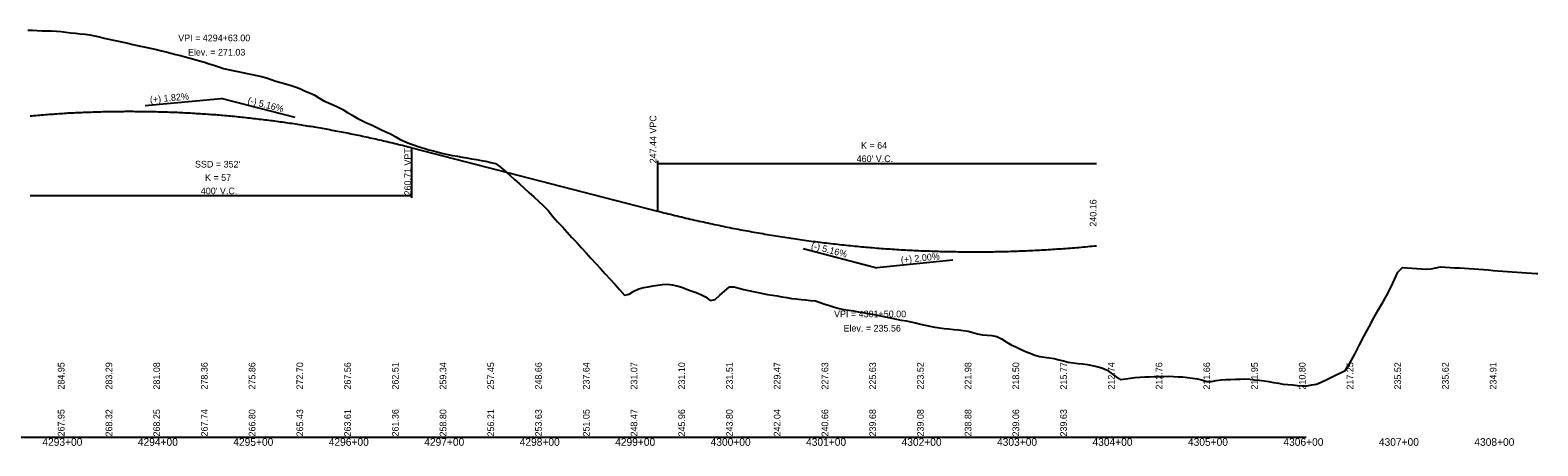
# Model space of a CAD drawing. Extents: x 1838386 to 1955906, y 719739 to 834437.
# Drawn here: x 1916207 to 1917787, y 768480 to 768916 of the extents above; entities that cross this region are included whole.
import ezdxf

# ---------------------------------------------------------------- set-up
doc = ezdxf.new("R2010")
doc.units = 0
for name, color, linetype in [('RD_DDB_GradeTX', 7, 'Continuous'), ('RD_DDB_Profile_EX', 7, 'Continuous'), ('RD_DDB_Profile_Lbl', 7, 'Continuous'), ('RD_DDB_Profile_PR', 7, 'Continuous'), ('RD_DDB_StaTX', 7, 'Continuous'), ('RD_DDB_StripGrade', 7, 'Continuous'), ('RD_DDB_VCLbl', 7, 'Continuous'), ('RD_GPK_Profile_Cell', 7, 'Continuous')]:
    doc.layers.add(name, color=color, linetype=linetype)

msp = doc.modelspace()

# ---------------------------------------------------------------- linework, layer by layer
at = {"layer": 'RD_DDB_GradeTX'}
for p, q in [((1916327.6, 768837.1), (1916407.2, 768844.3)), ((1916484.7, 768824.3), (1916407.2, 768844.3)), ((1917016.8, 768686.9), (1917094.2, 768666.9)), ((1917173.8, 768674.9), (1917094.2, 768666.9))]:
    msp.add_line(p, q, dxfattribs=at)
at = {"layer": 'RD_DDB_Profile_EX'}
for points in [[(1916204.7, 768916), (1916209.7, 768915.8), (1916214.7, 768915.6), (1916219.7, 768915.4), (1916224.7, 768915.3), (1916229.7, 768915.1), (1916234.7, 768914.9), (1916239.7, 768914.4), (1916244.7, 768913.8), (1916249.7, 768913.3), (1916254.7, 768912.7), (1916259.7, 768912.2), (1916264.7, 768911.7), (1916269.7, 768911), (1916274.7, 768909.9), (1916279.7, 768908.8), (1916284.7, 768907.7), (1916289.7, 768906.6), (1916294.7, 768905.5), (1916299.7, 768904.4), (1916304.7, 768903.3), (1916309.7, 768902.2), (1916314.7, 768901.1), (1916319.7, 768900), (1916324.7, 768898.9), (1916329.7, 768897.8), (1916334.7, 768896.7), (1916339.7, 768895.6), (1916344.7, 768894.4), (1916349.7, 768893.3), (1916354.7, 768892), (1916359.7, 768890.6), (1916364.7, 768889.3), (1916369.7, 768887.9), (1916374.7, 768886.5), (1916379.7, 768885.1), (1916384.7, 768883.8)], [(1916384.7, 768883.8), (1916389.7, 768882.4), (1916394.7, 768880.8), (1916399.7, 768879.2), (1916404.7, 768877.5), (1916409.7, 768875.9), (1916414.7, 768874.8), (1916419.7, 768873.7), (1916424.7, 768872.7), (1916429.7, 768871.6), (1916434.7, 768870.6), (1916439.7, 768869.5), (1916444.7, 768868.3), (1916449.7, 768867.2), (1916454.7, 768866), (1916459.7, 768864.2), (1916464.7, 768862.6), (1916469.7, 768861.1), (1916474.7, 768859.7), (1916479.7, 768858.2), (1916484.7, 768856.6), (1916489.7, 768854.8), (1916494.7, 768852.4), (1916499.7, 768850.4), (1916504.7, 768848.1), (1916509.7, 768845), (1916514.7, 768842), (1916519.7, 768839.9), (1916524.7, 768837.6), (1916529.7, 768835.1), (1916534.7, 768832.8), (1916539.7, 768829.7), (1916544.7, 768826.7), (1916549.7, 768823.7), (1916554.7, 768821.2), (1916559.7, 768818.9), (1916564.7, 768816.6), (1916569.7, 768814.2), (1916574.7, 768811.8), (1916579.7, 768809.4), (1916584.7, 768807.1), (1916589.7, 768804.5), (1916594.7, 768801.4), (1916599.7, 768799.1), (1916604.7, 768797.1), (1916609.7, 768795.3), (1916614.7, 768793.7), (1916619.7, 768792.1), (1916624.7, 768790.5), (1916629.7, 768789.3), (1916634.7, 768788), (1916639.7, 768786.8), (1916644.7, 768785.7), (1916649.7, 768784.7), (1916654.7, 768783.7), (1916659.7, 768782.8), (1916664.7, 768782), (1916669.7, 768781.2), (1916674.7, 768780.3), (1916679.7, 768779.4), (1916684.7, 768778.5), (1916689.7, 768777.3), (1916694.7, 768776.3), (1916699.7, 768772.5), (1916704.7, 768768.2), (1916709.7, 768763.8), (1916714.7, 768759.4), (1916719.7, 768754.8), (1916724.7, 768750.1), (1916729.7, 768745.6), (1916734.7, 768741.2), (1916739.7, 768736.7), (1916744.7, 768732), (1916749.7, 768726.7), (1916754.7, 768720.5), (1916759.7, 768715), (1916764.7, 768709.6), (1916769.7, 768704.1), (1916774.7, 768698.7), (1916779.7, 768693.2), (1916784.7, 768687.7), (1916789.7, 768682.3), (1916794.7, 768676.8), (1916799.7, 768671.4), (1916804.7, 768665.9), (1916809.7, 768660.4), (1916814.7, 768655), (1916819.7, 768649.5), (1916824.7, 768643.9), (1916829.7, 768638.1), (1916834.7, 768639.1), (1916839.7, 768642.4), (1916844.7, 768644.7), (1916849.7, 768646), (1916854.7, 768646.9), (1916859.7, 768647.8), (1916864.7, 768648.5), (1916869.7, 768649.3), (1916874.7, 768649.6), (1916879.7, 768648.8), (1916884.7, 768647.9)], [(1917384.7, 768552.8), (1917389.7, 768552.8), (1917394.7, 768552.9), (1917399.7, 768553.1), (1917404.7, 768552.9), (1917409.7, 768552.6), (1917414.7, 768552.4), (1917419.7, 768551.8), (1917424.7, 768551.1), (1917429.7, 768550.4), (1917434.7, 768549.2), (1917439.7, 768547.5), (1917444.7, 768547.4), (1917449.7, 768548.6), (1917454.7, 768549.2), (1917459.7, 768549.5), (1917464.7, 768549.8), (1917469.7, 768550), (1917474.7, 768550.1), (1917479.7, 768550.4), (1917484.7, 768550.1), (1917489.7, 768549.4), (1917494.7, 768548.8), (1917499.7, 768548.2), (1917504.7, 768547.4), (1917509.7, 768546.5), (1917514.7, 768545.7), (1917519.7, 768544.8), (1917524.7, 768544.4), (1917529.7, 768543.9), (1917534.7, 768543.4), (1917539.7, 768543.1), (1917544.7, 768543.1), (1917549.7, 768544), (1917554.7, 768544.8), (1917559.7, 768547), (1917564.7, 768549.4), (1917569.7, 768551.8), (1917574.7, 768554.2), (1917579.7, 768556.6), (1917584.7, 768559), (1917589.7, 768566.6), (1917594.7, 768576.3), (1917599.7, 768585.9), (1917604.7, 768595.5), (1917609.7, 768605), (1917614.7, 768614.4), (1917619.7, 768623.1), (1917624.7, 768631.9), (1917629.7, 768640.6), (1917634.7, 768650.5), (1917639.7, 768662.1), (1917644.7, 768667.2), (1917649.7, 768666.8), (1917654.7, 768666.4), (1917659.7, 768666), (1917664.7, 768665.6), (1917669.7, 768665.3), (1917674.7, 768665.7), (1917679.7, 768666.6), (1917684.7, 768667.8), (1917689.7, 768667.5), (1917694.7, 768667.2), (1917699.7, 768666.9), (1917704.7, 768666.6), (1917709.7, 768666.3), (1917714.7, 768665.9), (1917719.7, 768665.6), (1917724.7, 768665.2), (1917729.7, 768664.9), (1917734.7, 768664.5), (1917739.7, 768664.1), (1917744.7, 768663.7), (1917749.7, 768663.3), (1917754.7, 768662.9), (1917759.7, 768662.5), (1917764.7, 768662.2), (1917769.7, 768661.9), (1917774.7, 768661.5), (1917779.7, 768661.2), (1917784.7, 768660.9), (1917786.5, 768660.7)], [(1916884.7, 768647.9), (1916889.7, 768646.5), (1916894.7, 768644.5), (1916899.7, 768642.6), (1916904.7, 768640.7), (1916909.7, 768638.8), (1916914.7, 768636.4), (1916919.7, 768632.5), (1916924.7, 768633.5), (1916929.7, 768637.9), (1916934.7, 768642.3), (1916939.7, 768646.7), (1916944.7, 768646.7), (1916949.7, 768645.4), (1916954.7, 768643.9), (1916959.7, 768642.9), (1916964.7, 768641.9), (1916969.7, 768640.9), (1916974.7, 768639.8), (1916979.7, 768638.8), (1916984.7, 768638), (1916989.7, 768637.2), (1916994.7, 768636.4), (1916999.7, 768635.6), (1917004.7, 768634.7), (1917009.7, 768634.2), (1917014.7, 768633.7), (1917019.7, 768633.2), (1917024.7, 768632.6), (1917029.7, 768632.1), (1917034.7, 768630.5), (1917039.7, 768628.8), (1917044.7, 768627.1), (1917049.7, 768625.4), (1917054.7, 768624), (1917059.7, 768623.2), (1917064.7, 768622.4), (1917069.7, 768621.5), (1917074.7, 768620.7), (1917079.7, 768619.8), (1917084.7, 768619), (1917089.7, 768618.2), (1917094.7, 768617.2), (1917099.7, 768616.1), (1917104.7, 768615), (1917109.7, 768614), (1917114.7, 768613), (1917119.7, 768612), (1917124.7, 768611), (1917129.7, 768610), (1917134.7, 768608.9), (1917139.7, 768607.8), (1917144.7, 768606.7), (1917149.7, 768605.5), (1917154.7, 768604.4), (1917159.7, 768603.7), (1917164.7, 768603.2), (1917169.7, 768602.7), (1917174.7, 768602.1), (1917179.7, 768601.6), (1917184.7, 768601.1), (1917189.7, 768600.4), (1917194.7, 768598.9), (1917199.7, 768597.4), (1917204.7, 768596.5), (1917209.7, 768596.1), (1917214.7, 768595.7), (1917219.7, 768594.7), (1917224.7, 768592.4), (1917229.7, 768589.3), (1917234.7, 768586.1), (1917239.7, 768583.8), (1917244.7, 768581.4), (1917249.7, 768579), (1917254.7, 768577.1), (1917259.7, 768575.2), (1917264.7, 768573.6), (1917269.7, 768572.9), (1917274.7, 768572.2), (1917279.7, 768571.5), (1917284.7, 768570.4), (1917289.7, 768569.1), (1917294.7, 768567.9), (1917299.7, 768567), (1917304.7, 768566.5), (1917309.7, 768566), (1917314.7, 768565.5), (1917319.7, 768564.4), (1917324.7, 768563.1), (1917329.7, 768561.7), (1917334.7, 768559.9), (1917339.7, 768556.2), (1917344.7, 768552.5), (1917349.7, 768549.5), (1917354.7, 768550.3), (1917359.7, 768551.1), (1917364.7, 768551.8), (1917369.7, 768552.1), (1917374.7, 768552.3), (1917379.7, 768552.6), (1917384.7, 768552.8)]]:
    msp.add_lwpolyline(points, dxfattribs=at)
at = {"layer": 'RD_DDB_Profile_PR'}
msp.add_line((1916607.2, 768792.7), (1916864.2, 768726.3), dxfattribs=at)
for points in [[(1916207.2, 768826.1), (1916215.2, 768826.8), (1916223.2, 768827.5), (1916231.2, 768828), (1916239.2, 768828.6), (1916247.2, 768829.1), (1916255.2, 768829.5), (1916263.2, 768829.8), (1916271.2, 768830.1), (1916279.2, 768830.4), (1916287.2, 768830.6), (1916295.2, 768830.7), (1916303.2, 768830.8), (1916311.2, 768830.9), (1916319.2, 768830.8), (1916327.2, 768830.7), (1916335.2, 768830.6), (1916343.2, 768830.4), (1916351.2, 768830.2), (1916359.2, 768829.9), (1916367.2, 768829.5), (1916375.2, 768829.1), (1916383.2, 768828.6), (1916391.2, 768828.1), (1916399.2, 768827.5), (1916407.2, 768826.9), (1916415.2, 768826.2), (1916423.2, 768825.4), (1916431.2, 768824.6), (1916439.2, 768823.7), (1916447.2, 768822.8), (1916455.2, 768821.8), (1916463.2, 768820.8), (1916471.2, 768819.7), (1916479.2, 768818.6), (1916487.2, 768817.4), (1916495.2, 768816.1), (1916503.2, 768814.8), (1916511.2, 768813.4), (1916519.2, 768812), (1916527.2, 768810.5), (1916535.2, 768809), (1916543.2, 768807.4), (1916551.2, 768805.8), (1916559.2, 768804.1), (1916567.2, 768802.3), (1916575.2, 768800.5), (1916583.2, 768798.6), (1916591.2, 768796.7), (1916599.2, 768794.7), (1916607.2, 768792.7)], [(1916864.2, 768726.3), (1916873.4, 768724), (1916882.6, 768721.7), (1916891.8, 768719.5), (1916901, 768717.3), (1916910.2, 768715.3), (1916919.4, 768713.3), (1916928.6, 768711.3), (1916937.8, 768709.4), (1916947, 768707.6), (1916956.2, 768705.9), (1916965.4, 768704.2), (1916974.6, 768702.6), (1916983.8, 768701), (1916993, 768699.5), (1917002.2, 768698.1), (1917011.4, 768696.8), (1917020.6, 768695.5), (1917029.8, 768694.2), (1917039, 768693.1), (1917048.2, 768692), (1917057.4, 768691), (1917066.6, 768690), (1917075.8, 768689.1), (1917085, 768688.3), (1917094.2, 768687.5), (1917103.4, 768686.8), (1917112.6, 768686.2), (1917121.8, 768685.6), (1917131, 768685.2), (1917140.2, 768684.7), (1917149.4, 768684.4), (1917158.6, 768684.1), (1917167.8, 768683.8), (1917177, 768683.7), (1917186.2, 768683.6), (1917195.4, 768683.5), (1917204.6, 768683.5), (1917213.8, 768683.6), (1917223, 768683.8), (1917232.2, 768684), (1917241.4, 768684.3), (1917250.6, 768684.7), (1917259.8, 768685.1), (1917269, 768685.6), (1917278.2, 768686.2), (1917287.4, 768686.8), (1917296.6, 768687.5), (1917305.8, 768688.2), (1917315, 768689.1), (1917324.2, 768689.9)]]:
    msp.add_spline(points, degree=3, dxfattribs=at)
at = {"layer": 'RD_DDB_VCLbl'}
for p, q in [((1916607.2, 768740.2), (1916607.2, 768792.7)), ((1916864.2, 768778.8), (1916864.2, 768726.3)), ((1916864.2, 768776.3), (1917324.2, 768776.3)), ((1916207.2, 768742.7), (1916607.2, 768742.7))]:
    msp.add_line(p, q, dxfattribs=at)
at = {"layer": 'RD_GPK_Profile_Cell'}
msp.add_line((1914544, 768489.1), (1917544, 768489.1), dxfattribs=at)

# ---------------------------------------------------------------- texts
at = {"layer": 'RD_DDB_GradeTX'}
for s, rotation, p in [('(+) 1.82%', 5.2009, (1916333, 768839.6)), ('(-) 5.16%', 345.5232, (1916434.5, 768839.3)), ('(-) 5.16%', 345.5232, (1917024.7, 768687)), ('(+) 2.00%', 5.7106, (1917119.6, 768671.5))]:
    msp.add_text(s, height=7, rotation=rotation, dxfattribs=at).set_placement(p)
at = {"layer": 'RD_DDB_Profile_Lbl'}
for s, p in [('VPI = 4294+63.00', (1916362.3, 768904.3)), ('Elev. = 271.03', (1916372.5, 768889.3)), ('VPI = 4301+50.00', (1917049.3, 768614.9)), ('Elev. = 235.56', (1917059.2, 768599.9))]:
    msp.add_text(s, height=7, dxfattribs=at).set_placement(p)
msp.add_text('240.16', height=7, rotation=90, dxfattribs=at).set_placement((1917324.2, 768709.9))
at = {"layer": 'RD_DDB_StaTX'}
for s, p in [('4293+00', (1916220, 768480.1)), ('4294+00', (1916320, 768480.1)), ('4295+00', (1916420, 768480.1)), ('4296+00', (1916520, 768480.1)), ('4297+00', (1916620, 768480.1)), ('4298+00', (1916720, 768480.1)), ('4299+00', (1916820, 768480.1)), ('4300+00', (1916920, 768480.1)), ('4301+00', (1917020, 768480.1)), ('4302+00', (1917120, 768480.1)), ('4303+00', (1917220, 768480.1)), ('4304+00', (1917320, 768480.1)), ('4305+00', (1917420, 768480.1)), ('4306+00', (1917520, 768480.1)), ('4307+00', (1917620, 768480.1)), ('4308+00', (1917720, 768480.1))]:
    msp.add_text(s, height=8, dxfattribs=at).set_placement(p)
at = {"layer": 'RD_DDB_StripGrade'}
for s, p in [('247.44 VPC', (1916863.2, 768776.3)), ('260.71 VPT', (1916606.2, 768742.7)), ('284.95', (1916243.2, 768539.1)), ('283.29', (1916293.2, 768539.1)), ('281.08', (1916343.2, 768539.1)), ('278.36', (1916393.2, 768539.1)), ('275.86', (1916443.2, 768539.1)), ('272.70', (1916493.2, 768539.1)), ('267.56', (1916543.2, 768539.1)), ('262.51', (1916593.2, 768539.1)), ('259.34', (1916643.2, 768539.1)), ('257.45', (1916693.2, 768539.1)), ('248.66', (1916743.2, 768539.1)), ('237.64', (1916793.2, 768539.1)), ('231.07', (1916843.2, 768539.1)), ('231.10', (1916893.2, 768539.1)), ('231.51', (1916943.2, 768539.1)), ('229.47', (1916993.2, 768539.1)), ('227.63', (1917043.2, 768539.1)), ('225.63', (1917093.2, 768539.1)), ('223.52', (1917143.2, 768539.1)), ('221.98', (1917193.2, 768539.1)), ('218.50', (1917243.2, 768539.1)), ('215.77', (1917293.2, 768539.1)), ('212.74', (1917343.2, 768539.1)), ('212.76', (1917393.2, 768539.1)), ('211.66', (1917443.2, 768539.1)), ('211.95', (1917493.2, 768539.1)), ('210.80', (1917543.2, 768539.1)), ('217.25', (1917593.2, 768539.1)), ('235.52', (1917643.2, 768539.1)), ('235.62', (1917693.2, 768539.1)), ('234.91', (1917743.2, 768539.1)), ('267.95', (1916243.2, 768489.9)), ('268.32', (1916293.2, 768489.9)), ('268.25', (1916343.2, 768489.9)), ('267.74', (1916393.2, 768489.9)), ('266.80', (1916443.2, 768489.9)), ('265.43', (1916493.2, 768489.9)), ('263.61', (1916543.2, 768489.9)), ('261.36', (1916593.2, 768489.9)), ('258.80', (1916643.2, 768489.9)), ('256.21', (1916693.2, 768489.9)), ('253.63', (1916743.2, 768489.9)), ('251.05', (1916793.2, 768489.9)), ('248.47', (1916843.2, 768489.9)), ('245.96', (1916893.2, 768489.9)), ('243.80', (1916943.2, 768489.9)), ('242.04', (1916993.2, 768489.9)), ('240.66', (1917043.2, 768489.9)), ('239.68', (1917093.2, 768489.9)), ('239.08', (1917143.2, 768489.9)), ('238.88', (1917193.2, 768489.9)), ('239.06', (1917243.2, 768489.9)), ('239.63', (1917293.2, 768489.9))]:
    msp.add_text(s, height=7, rotation=90, dxfattribs=at).set_placement(p)
at = {"layer": 'RD_DDB_VCLbl'}
for s, p in [('K = 64', (1917077.6, 768791.6)), ("SSD = 352'", (1916379.9, 768771.9)), ("460' V.C.", (1917073, 768777.6)), ('K = 57', (1916390.4, 768757.9)), ("400' V.C.", (1916386, 768743.9))]:
    msp.add_text(s, height=7, dxfattribs=at).set_placement(p)

doc.saveas('drawing.dxf')
